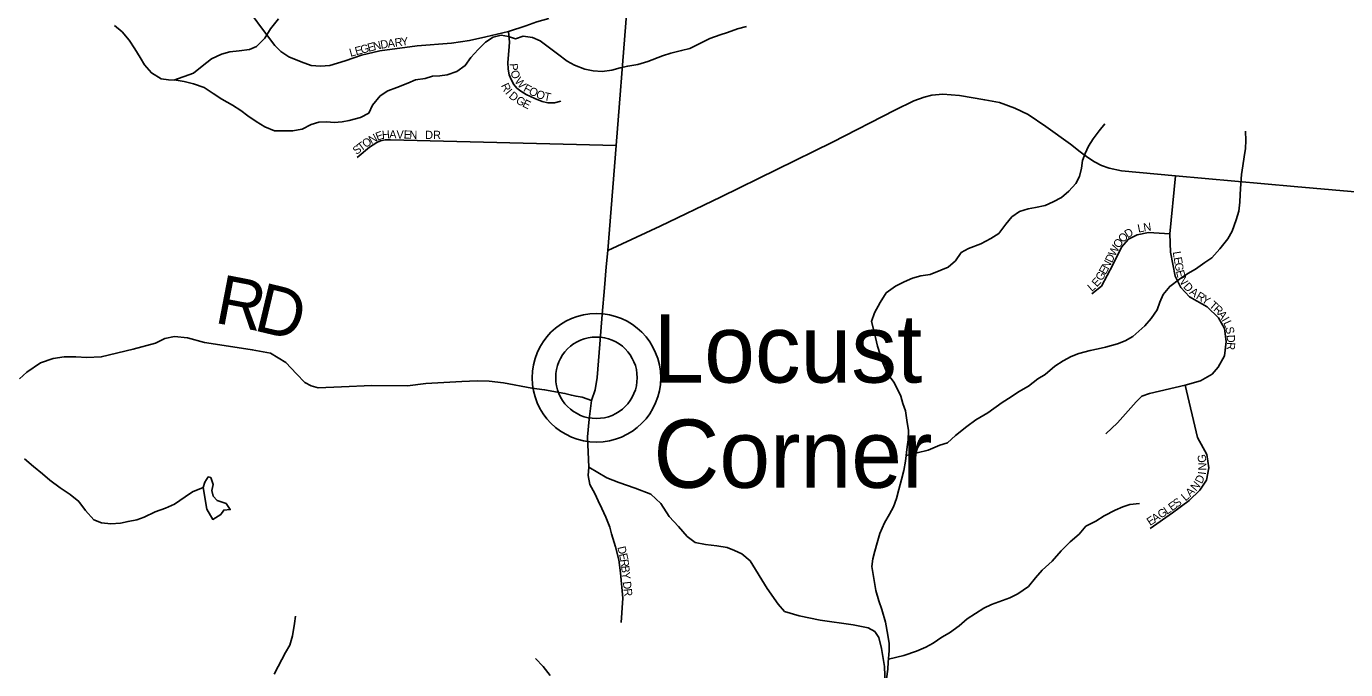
# Model space of a CAD drawing. Extents: x 1310247 to 1664935, y 235267 to 584339.
# Drawn here: x 1460622 to 1468683, y 376395 to 380323 of the extents above; entities that cross this region are included whole.
import ezdxf

# ---------------------------------------------------------------- set-up
doc = ezdxf.new("R2010")
doc.units = 0
for name, color, linetype in [('GM_X_County_Road', 7, 'Continuous'), ('GM_X_County_Road_Text', 7, 'Continuous'), ('GM_X_Minor_Lake', 7, 'Continuous'), ('GM_X_Minor_River', 7, 'Continuous'), ('GM_X_Township_Road', 7, 'Continuous'), ('GM_X_Township_Subdivision', 7, 'Continuous'), ('GM_X_Township_Subdivision_Text', 7, 'Continuous'), ('GM_X_Unincorporated', 7, 'Continuous'), ('GM_X_Unincorporated_Location', 7, 'Continuous'), ('GM_X_Unincorporated_Text', 7, 'Continuous')]:
    doc.layers.add(name, color=color, linetype=linetype)

msp = doc.modelspace()

# ---------------------------------------------------------------- linework, layer by layer
at = {"layer": 'GM_X_County_Road'}
for points in [[(1464175.4, 378953.9), (1464493.6, 379102.6), (1464866.9, 379282.9), (1465548.1, 379616.7), (1465927.7, 379810.7), (1466045.2, 379868.1), (1466107.4, 379891.7), (1466153.6, 379902.6), (1466221.3, 379909.2), (1466324.3, 379900.1), (1466477.3, 379874), (1466567.2, 379858.9), (1466660.5, 379824.4), (1466742, 379784.9), (1466851.3, 379711.8), (1467001.8, 379604.2), (1467060.6, 379557.1), (1467106.8, 379521.8), (1467148, 379495.8), (1467190.9, 379473.9), (1467238, 379456.3), (1467312.8, 379441.1), (1467643.3, 379410.9), (1468368.5, 379344.5), (1469226.9, 379269.4)], [(1460579.4, 378169.6), (1460625.1, 378211.3), (1460707.7, 378268.2), (1460785.3, 378294.6), (1460853.3, 378304.3), (1460924, 378304.3), (1460991.9, 378300.1), (1461079.3, 378304.3), (1461274.3, 378352.7), (1461411.4, 378389.2), (1461467.5, 378416.2), (1461526.7, 378428.8), (1461606.2, 378421.3), (1461710.8, 378393.5), (1461908.7, 378362), (1462001.9, 378348.2), (1462112.9, 378326.7), (1462207.4, 378270), (1462271.7, 378201.9), (1462322.1, 378147.7), (1462361.2, 378127.6), (1462404, 378116.2), (1462547.7, 378121.3), (1462733, 378130.1), (1462950.8, 378127.1), (1463062.7, 378142.7), (1463282.8, 378154.7), (1463376.7, 378158.4), (1463449.5, 378155.6), (1463536.1, 378145.5), (1463711, 378113.2), (1463788, 378104.2), (1463911.8, 378081.9), (1463951.5, 378069.9), (1463980.9, 378064.4), (1464017.8, 378058), (1464075.5, 378039.2), (1464098, 378104.1), (1464108.3, 378179.1), (1464124.9, 378381.8), (1464140.3, 378563.6), (1464153.5, 378725.9), (1464164.2, 378854.7), (1464175.4, 378953.9)]]:
    msp.add_lwpolyline(points, dxfattribs=at)
at = {"layer": 'GM_X_Minor_Lake'}
msp.add_lwpolyline([(1461702, 377506.6), (1461725.1, 377374.9), (1461760, 377312), (1461808.7, 377341.1), (1461827.3, 377368.8), (1461867.4, 377372), (1461842.1, 377408.7), (1461786.3, 377427.8), (1461762.8, 377454.4), (1461755.5, 377488.7), (1461762.2, 377524.7), (1461749, 377567.1)], dxfattribs=at)
at = {"layer": 'GM_X_Minor_River'}
for points in [[(1461159.3, 380328), (1461206.8, 380289), (1461250.2, 380240), (1461283.4, 380185.2), (1461316.6, 380132.4), (1461344, 380087.8), (1461385.3, 380038.8), (1461444.9, 380003.6), (1461489, 379996.8), (1461537.1, 379994), (1461585.2, 379987.1), (1461643.1, 379972), (1461707, 379950.8), (1461762.6, 379913.7), (1461816.2, 379878.6), (1461881.8, 379841.3), (1461931.5, 379810.3), (1461975.1, 379777.5), (1462024.7, 379742.4), (1462078.3, 379709.4), (1462138.1, 379686.2), (1462248.5, 379684.3), (1462306.9, 379695.3), (1462361.6, 379724.5), (1462408, 379737.7), (1462458.2, 379740.9)], [(1461522.4, 379994.9), (1461642.2, 380038.3), (1461695.1, 380079.6), (1461752.1, 380124.8), (1461814.8, 380153.8), (1461865.2, 380167), (1461921.5, 380174.1), (1461983.9, 380183), (1462028.4, 380200.3), (1462079.4, 380251.6), (1462112.5, 380307.3), (1462161.7, 380368.7)], [(1462458.2, 379740.9), (1462502.3, 379736.1), (1462550.5, 379739.3), (1462594.9, 379748.5), (1462663.4, 379767.4), (1462714, 379792.6), (1462737, 379842.5), (1462784.1, 379899.9), (1462830.8, 379929.2), (1462885.3, 379950.3), (1462952, 379977.3), (1462998.5, 379996.5), (1463058.9, 380005.5), (1463103.3, 380018.8), (1463147.5, 380022.1), (1463193.7, 380027.3), (1463252.3, 380048.3), (1463303.1, 380083.6), (1463338.1, 380133.2), (1463383, 380182.6), (1463427.9, 380226), (1463474.6, 380257.3), (1463523, 380268.6), (1463567.1, 380261.8), (1463611, 380246.9), (1463657.4, 380264.2), (1463713.5, 380255.2), (1463761.3, 380234.3), (1463810.9, 380199.2), (1463866.4, 380156.1), (1463925.8, 380110.9), (1463971.6, 380086), (1464033.4, 380062.8), (1464085.4, 380051.8), (1464139.5, 380046.9), (1464199.9, 380055.9), (1464250.4, 380071), (1464296.7, 380080.3), (1464357.1, 380091.3), (1464419.6, 380108.3), (1464508.5, 380142.9), (1464559, 380160), (1464625.5, 380175), (1464675.9, 380188.1), (1464732.6, 380217.3), (1464797.3, 380248.3), (1464860, 380271.3), (1464906.4, 380286.5), (1464967, 380307.6), (1465021.4, 380322.7)], [(1465998.2, 377703.1), (1466132, 377734.3), (1466202.8, 377765.2), (1466249.3, 377780.5), (1466298.2, 377823.8), (1466367.3, 377878.9), (1466422.2, 377920.1), (1466497.2, 377962.9), (1466584.6, 378025.7), (1466639.4, 378060.9), (1466684, 378090.2), (1466744.9, 378125.3), (1466801.8, 378170.5), (1466846.4, 378197.9), (1466905.5, 378247), (1466956.2, 378280.3), (1467004.9, 378307.6), (1467053.3, 378324.8), (1467121.9, 378343.7), (1467170.2, 378352.9), (1467214.6, 378364.2), (1467289.2, 378385), (1467335.7, 378402.2), (1467382.3, 378429.5), (1467455.7, 378494.5), (1467494.6, 378540), (1467531.6, 378591.6), (1467548.4, 378639.5), (1467567.3, 378685.4), (1467608.3, 378734.9), (1467667.2, 378780), (1467718, 378813.3), (1467764.6, 378840.6), (1467821.5, 378881.8), (1467866.1, 378909.1), (1467913.2, 378964.5), (1467962.4, 379025.9), (1467989.3, 379071.7), (1468014.6, 379141.5), (1468029.5, 379195.5), (1468036.5, 379249.6), (1468039.3, 379295.7), (1468042.4, 379364), (1468047.3, 379418.1), (1468054.3, 379472.2), (1468063.2, 379526.3), (1468070.1, 379576.4), (1468072.9, 379626.6), (1468071.9, 379682.8)], [(1466144.1, 378808.7), (1466208.8, 378833.7), (1466253.3, 378853), (1466298.1, 378890.4), (1466333.1, 378942), (1466377.6, 378967.3), (1466454.4, 378996.1), (1466515.2, 379027.2), (1466563.9, 379058.5), (1466607, 379115.9), (1466643.8, 379159.5), (1466690.6, 379192.8), (1466743, 379208), (1466787.3, 379217.2), (1466847.8, 379230.2), (1466896.3, 379251.5), (1466947, 379278.7), (1466991.7, 379316.1), (1467034.7, 379363.5), (1467057.5, 379407.3), (1467068.4, 379457.3), (1467075.2, 379503.4), (1467092, 379547.3), (1467110.8, 379591.2), (1467139.7, 379636.9), (1467176.6, 379684.4), (1467211.5, 379728)], [(1465877.7, 376338.8), (1465884.7, 376396.9), (1465887.4, 376441.1), (1465892.6, 376509.3), (1465893.3, 376553.5), (1465886.2, 376605.8), (1465871.5, 376684.4), (1465848.7, 376761.1), (1465829.5, 376815.7), (1465812.5, 376878.3), (1465799.7, 376950.8), (1465786.9, 377025.3), (1465793.7, 377071.4), (1465806.5, 377117.4), (1465819.4, 377169.4), (1465836.4, 377225.3), (1465865.6, 377291.1), (1465896.6, 377344.8), (1465919.5, 377388.6), (1465938.4, 377440.5), (1465953.4, 377494.4), (1465968.5, 377556.4), (1465983.4, 377610.4), (1465994.4, 377668.5), (1466003.9, 377754.7), (1466008.7, 377798.8), (1466011.6, 377855), (1466000.6, 377917.4), (1465993.6, 377975.8), (1465976.3, 378020.3), (1465965, 378064.7), (1465924.2, 378147.7), (1465883, 378200.7), (1465854, 378267.5), (1465821.6, 378370.5), (1465804.8, 378449.1), (1465786, 378521.7), (1465804.9, 378573.6), (1465838.1, 378637.3), (1465875.2, 378694.9), (1465932.1, 378736.1), (1465984.8, 378763.3), (1466035.3, 378784.5), (1466087.8, 378799.6), (1466144.1, 378808.7)], [(1460610.9, 377682.3), (1460664.3, 377635.2), (1460719.7, 377590), (1460765.3, 377551.1), (1460828.7, 377505.8), (1460888.3, 377464.6), (1460941.7, 377421.5), (1460983, 377366.5), (1461034.2, 377309.4), (1461080, 377290.5), (1461138.2, 377285.5), (1461196.4, 377288.5), (1461242.8, 377299.7), (1461297.1, 377308.8), (1461341.6, 377326.1), (1461408.4, 377359.1), (1461471, 377380.1), (1461527.6, 377405.2), (1461592.6, 377450.2), (1461637.3, 377479.6), (1461702, 377506.6)], [(1461749, 377567.1), (1461733, 377571.4), (1461712.4, 377539.7), (1461702, 377506.6)], [(1465888.7, 376457.9), (1465982.5, 376481.6), (1466061.2, 376506.3), (1466117.8, 376531.5), (1466162.4, 376556.8), (1466215.2, 376592), (1466261.8, 376619.3), (1466320.7, 376662.5), (1466369.6, 376703.8), (1466471.1, 376770.3), (1466519.6, 376791.6), (1466630.8, 376833.8), (1466679.3, 376857.1), (1466744.3, 376902.1), (1466787.4, 376955.6), (1466828.3, 377001.1), (1466889.4, 377056.2), (1466944.7, 377119.5), (1466999.8, 377174.8), (1467054.8, 377222.1), (1467095.8, 377271.6), (1467156.5, 377300.6), (1467207.3, 377333.9), (1467274.1, 377368.9), (1467320.6, 377388.1), (1467365, 377403.5), (1467423.3, 377408.5)], [(1462136.4, 376366.1), (1462159.3, 376413.9), (1462204.9, 376499.5), (1462231.7, 376543.2), (1462246.7, 376601.2), (1462260.1, 376677.3), (1462266.8, 376721.4)], [(1463822.5, 376358.7), (1463779.2, 376413.7), (1463731.9, 376462.8)]]:
    msp.add_lwpolyline(points, dxfattribs=at)
at = {"layer": 'GM_X_Township_Road'}
for points in [[(1464175.4, 378953.9), (1464225.4, 379594.9), (1464283.8, 380344.7), (1464300.8, 380564.6), (1464392.8, 381730.7), (1464405.9, 381926.2), (1464437.5, 382455.9), (1464399.1, 382590.7)], [(1465869.5, 376305.8), (1465865, 376413.7), (1465847.3, 376523), (1465829.6, 376591), (1465805.9, 376626.5), (1465764.6, 376650.1), (1465674.4, 376667.8), (1465472, 376695.9), (1465343.5, 376722.5), (1465254.8, 376749.1), (1465216.2, 376795), (1465148.4, 376889.5), (1465043.5, 377059.4), (1464993.3, 377100.8), (1464948.9, 377123), (1464904.6, 377140.7), (1464839.6, 377151), (1464771.6, 377158.4), (1464708.1, 377171.7), (1464659.3, 377207.2), (1464606.1, 377269.2), (1464548.5, 377329.8), (1464498.3, 377409.6), (1464436.8, 377465.4), (1464342.3, 377503.4), (1464242.3, 377537.1), (1464168.5, 377566.3), (1464057.7, 377631.6), (1464050.1, 377816.2), (1464059.9, 377923.7), (1464075.5, 378039.2)]]:
    msp.add_lwpolyline(points, dxfattribs=at)
at = {"layer": 'GM_X_Township_Subdivision'}
for points in [[(1461982.1, 380416.4), (1462083.2, 380282), (1462138.9, 380205.6), (1462177.1, 380169.7), (1462225.8, 380137), (1462300, 380106.2), (1462362.5, 380085), (1462419.6, 380080), (1462475.3, 380085), (1462568.7, 380113.6), (1462670.1, 380147.2), (1462782.2, 380174.3), (1463009.2, 380205.2), (1463219.9, 380220.3), (1463328.5, 380237.8), (1463430, 380260.1), (1463566.5, 380292.1), (1463672.8, 380327.6), (1463741, 380351.5), (1463814.3, 380370.5)], [(1463886.3, 379866.4), (1463847.6, 379855.4), (1463808.5, 379856.3), (1463773.1, 379863.7), (1463728, 379882.1), (1463674.6, 379907.4), (1463642.4, 379927.2), (1463618.9, 379946.1), (1463601, 379969.1), (1463583, 379998.5), (1463571.1, 380027.1), (1463565.1, 380061.6), (1463563.7, 380103.4), (1463570.1, 380173.4), (1463573.7, 380227.5), (1463566.5, 380292.1)], [(1462642.4, 379522.9), (1462718.7, 379584.7), (1462762, 379613.6), (1462784.6, 379623.9), (1462813.5, 379630.1), (1462846.5, 379630.1), (1464225.4, 379594.9)], [(1467217.9, 377833.7), (1467289.2, 377902.5), (1467402.2, 378030.3), (1467436.7, 378064.8), (1467483.4, 378082), (1467702.1, 378131.1), (1467795.6, 378158.2), (1467866.8, 378200), (1467903.7, 378241.8), (1467943.1, 378310.6), (1467952.9, 378399.1), (1467943.1, 378477.8), (1467906.2, 378544.1), (1467837.4, 378610.5), (1467729.2, 378671.9), (1467675.1, 378728.5), (1467640.7, 378797.3), (1467613.7, 378944.8), (1467608.7, 379055.4), (1467643.3, 379410.9)], [(1467131.8, 378689.2), (1467190.8, 378735.9), (1467259.7, 378866.2), (1467313.8, 378974.3), (1467355.5, 379023.5), (1467409.6, 379050.5), (1467478.5, 379065.3), (1467608.7, 379055.4)], [(1467487.6, 377256.9), (1467625.1, 377351.7), (1467726.2, 377427.5), (1467792.5, 377490.7), (1467833.6, 377550.8), (1467846.2, 377626.6), (1467835.2, 377708.7), (1467778.3, 377811.4), (1467702.1, 378131.1)], [(1464255.9, 376682.6), (1464266.3, 376830.4), (1464252.1, 376986.5), (1464242.3, 377064.7), (1464220.6, 377144), (1464196.7, 377223.2), (1464185.9, 377264.5), (1464162, 377326.4), (1464138.1, 377379.6), (1464116.4, 377426.3), (1464094.6, 377469.8), (1464065.3, 377526.2), (1464054.5, 377579.5), (1464057.7, 377631.6)]]:
    msp.add_lwpolyline(points, dxfattribs=at)
at = {"layer": 'GM_X_Unincorporated'}
for radius in [392.8, 249]:
    msp.add_circle((1464104.8, 378177.1), radius, dxfattribs=at)
at = {"layer": 'GM_X_Unincorporated_Location'}
msp.add_line((1464104.8, 378177.1), (1464104.8, 378177.1), dxfattribs=at)

# ---------------------------------------------------------------- texts
at = {"layer": 'GM_X_County_Road_Text'}
for s, rotation, p in [('R', 349.08426, (1461764.6, 378514.7)), ('D', 346.55131, (1462003.1, 378468.8))]:
    msp.add_text(s, height=300, rotation=rotation, dxfattribs=at).set_placement(p)
at = {"layer": 'GM_X_Township_Subdivision_Text'}
for s, rotation, p in [('R', 7.79605, (1462875.1, 380198.5)), ('Y', 7.78387, (1462914.4, 380203.9)), ('L', 15.31501, (1462602.5, 380136.9)), ('E', 15.31501, (1462636.5, 380146.2)), ('G', 15.3437, (1462670.5, 380155.5)), ('E', 15.31501, (1462712.9, 380167.2)), ('N', 13.14041, (1462746.4, 380176.4)), ('D', 8.40214, (1462788.1, 380186.2)), ('A', 7.78387, (1462831.5, 380192.6)), ('P', 272.67824, (1463573.7, 380096.4)), ('O', 288.2134, (1463578, 380046.8)), ('W', 309.45921, (1463601.5, 379987.3)), ('R', 296.1524, (1463519.9, 379962.1)), ('I', 310.07188, (1463544.6, 379915.5)), ('D', 319.82164, (1463565.3, 379892)), ('F', 331.69269, (1463654.1, 379929.8)), ('O', 333.67136, (1463686.7, 379912.2)), ('O', 339.44953, (1463731.2, 379890.5)), ('G', 331.14389, (1463607.8, 379857.5)), ('E', 333.56076, (1463648.4, 379835.3)), ('T', 348.77327, (1463781, 379872.7)), ('E', 20.48251, (1462766.4, 379623.9)), ('H', 4.94513, (1462795.9, 379635.4)), ('A', 359.30051, (1462838.4, 379639.2)), ('V', 358.86342, (1462882.3, 379638.6)), ('E', 358.88968, (1462926.3, 379637.7)), ('N', 358.86342, (1462961.5, 379637.1)), ('DR', 0.00001, (1463058.3, 379635.6)), ('T', 37.0939, (1462667, 379558.1)), ('O', 34.84164, (1462694.6, 379579)), ('N', 28.82324, (1462729.6, 379603.5)), ('S', 37.0939, (1462638.9, 379536.9)), ('N', 8.11464, (1467450.3, 379070.2)), ('O', 45.44821, (1467322.3, 378998.4)), ('D', 32.23478, (1467350.8, 379027.9)), ('L', 11.30457, (1467416.5, 379063.4)), ('W', 63.11158, (1467273.7, 378914.5)), ('O', 55.28549, (1467298.6, 378964)), ('N', 61.83358, (1467232.7, 378834.7)), ('D', 63.80737, (1467254.4, 378875.2)), ('L', 279.35902, (1467626, 378945.5)), ('E', 279.35558, (1467631.7, 378910.8)), ('G', 279.35, (1467637.4, 378876)), ('G', 61.02805, (1467194.1, 378764.8)), ('E', 61.16843, (1467215.5, 378803.4)), ('E', 283.56686, (1467645.4, 378828.7)), ('N', 297.89054, (1467658.4, 378781.8)), ('L', 40.35829, (1467131.1, 378700.8)), ('E', 47.63608, (1467162.9, 378728.4)), ('D', 313.29536, (1467687.5, 378731)), ('A', 323.28048, (1467724.8, 378692.6)), ('R', 328.96081, (1467764.6, 378663.3)), ('Y', 328.51137, (1467798.4, 378642.9)), ('T', 318.80894, (1467844.7, 378613.5)), ('R', 316.42566, (1467870.8, 378590.6)), ('A', 306.46771, (1467898, 378565.1)), ('I', 300.47663, (1467923.4, 378530.8)), ('L', 294.38969, (1467933.9, 378513.1)), ('S', 281.10635, (1467947.5, 378484)), ('D', 273.80536, (1467956, 378438)), ('R', 266.08739, (1467958.9, 378395.9)), ('G', 95.70911, (1467832.2, 377660.8)), ('I', 82.92777, (1467828.6, 377582.8)), ('N', 88.97937, (1467831.7, 377610.4)), ('N', 49.5491, (1467767.6, 377481.3)), ('D', 63.28375, (1467803.4, 377525.6)), ('S', 36.23957, (1467650.4, 377381.4)), ('L', 40.86208, (1467704.1, 377421.2)), ('A', 45.17425, (1467733.8, 377447)), ('A', 33.70825, (1467517.5, 377290.8)), ('G', 33.73031, (1467554.1, 377315.3)), ('L', 34.15737, (1467591.1, 377339.9)), ('E', 35.80167, (1467621.5, 377360.6)), ('E', 33.70522, (1467488.2, 377271.3)), ('D', 282.62601, (1464232.8, 377142.4)), ('E', 282.41917, (1464242.4, 377099.5)), ('R', 277.59786, (1464249.7, 377066.2)), ('B', 276.54669, (1464255, 377027.2)), ('Y', 276.46088, (1464259.5, 376987.9)), ('D', 276.45258, (1464265.9, 376931)), ('R', 276.47726, (1464270.8, 376887.3))]:
    msp.add_text(s, height=50, rotation=rotation, dxfattribs=at).set_placement(p)
at = {"layer": 'GM_X_Unincorporated_Text'}
for s, p in [('Locust', (1464453.1, 378147.6)), ('Corner', (1464453.1, 377505.2))]:
    msp.add_text(s, height=417, rotation=0.00001, dxfattribs=at).set_placement(p)

doc.saveas('drawing.dxf')
